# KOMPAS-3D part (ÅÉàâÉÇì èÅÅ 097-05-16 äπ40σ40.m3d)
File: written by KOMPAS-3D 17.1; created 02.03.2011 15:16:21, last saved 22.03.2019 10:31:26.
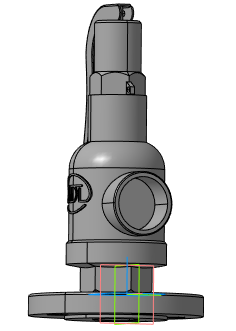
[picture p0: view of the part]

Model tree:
1. Плоскость XY
2. Плоскость ZX
3. Плоскость ZY
4. Ось X
5. Ось Y
6. Ось Z
7. Начало координат
8. Операция без истории:2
